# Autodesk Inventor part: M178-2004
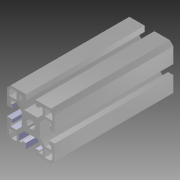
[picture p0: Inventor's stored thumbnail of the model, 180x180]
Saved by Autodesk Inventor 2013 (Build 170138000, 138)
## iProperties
Created: 2004-10
Material: Aluminium - 6061
Document SubType Name: Modeling
Designer: Autodesk, Inc.
Manufacturer: Standard
Standards Organization: Custom
Description: PC RACK, SIDE BAR
Stock Number: 10-540
Catalog Web Link: http://www.parker.com/ead/cm1.asp?cmid=809
Vendor: PARKER IPS
Part Number: M178-2004
Mass: 179.948 g
Surface Area: 483.565 cm^2
Volume: 66.4013 cm^3
Density: 2.71 g/cm^3
CAGE: 1LJX3
Dept. ID: Product Design
Description #2: ---
Finish #1: ---
Finish #2: ---
Material ID: ---
Project Number: ---
Stock Number: 10-040
Length: 461.000 mm
Author: Autodesk, Inc.
Revision Number: A
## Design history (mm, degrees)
derived "40 Series Profiles.ipt"
sketch "Sketch1"
  geometry: L1 (16, 461)-(16, 0) reference; L2 (0, 0)-(13, 0) reference; L3 (13, 0)-(16, 0) reference; L4 (1.625, 0)-(-9.625, 0) reference; L5 (-21, 0)-(-8, 0) reference; L6 (-24, 0)-(-21, 0) reference; L7 (-24, 0)-(16, 40)
  constraints: 2 end point, 1 point on line
  dimensions: "d3" = 45 deg angle of L1 L7
extrude "Extrusion1" cut sketch "Sketch1" stored distance "d1" = 10; taper "d2" = 0 deg
sketch "Sketch2"
  geometry: L1 (17, 92.2)-(17, -553.2) reference; L2 (11.375, -446.625)-(22.625, -435.375) reference; 3 further points
  constraints: 1 midpoint, 1 point on line
  dimensions: "d12" = 23.4 distance of point (17, -417.6) point (17, -441)
hole "Hole1" sketch "Sketch2" diameter "d5" = 4.917; stored, may be unused: countersink angle "d9" = 90 deg, drill point angle "d11" = 118 deg; dims "d6" = 6, "d7" = 4, "d8" = 2, "d10" = 8
mirror "Mirror1"
body "Solid1"
tag "TaggingFeature2"
feature "Solid1::40 Series Profiles.ipt" dims "ScaleForDerivedMember" = 10
other parameters: "Length" = 461
